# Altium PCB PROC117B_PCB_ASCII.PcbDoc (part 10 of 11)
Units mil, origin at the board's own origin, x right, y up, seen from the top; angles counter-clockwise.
Board outline 2480.32 x 3185.25 mil, 8 copper layers (Top Layer, L2_GND1, L3_SIG1, L4_PWR1, L5_PWR2, L6_SIG2, L7_GND2, Bottom Layer), stack 57.4 mil thick; 456 components, 292 nets, 7831 pads, 2905 vias.
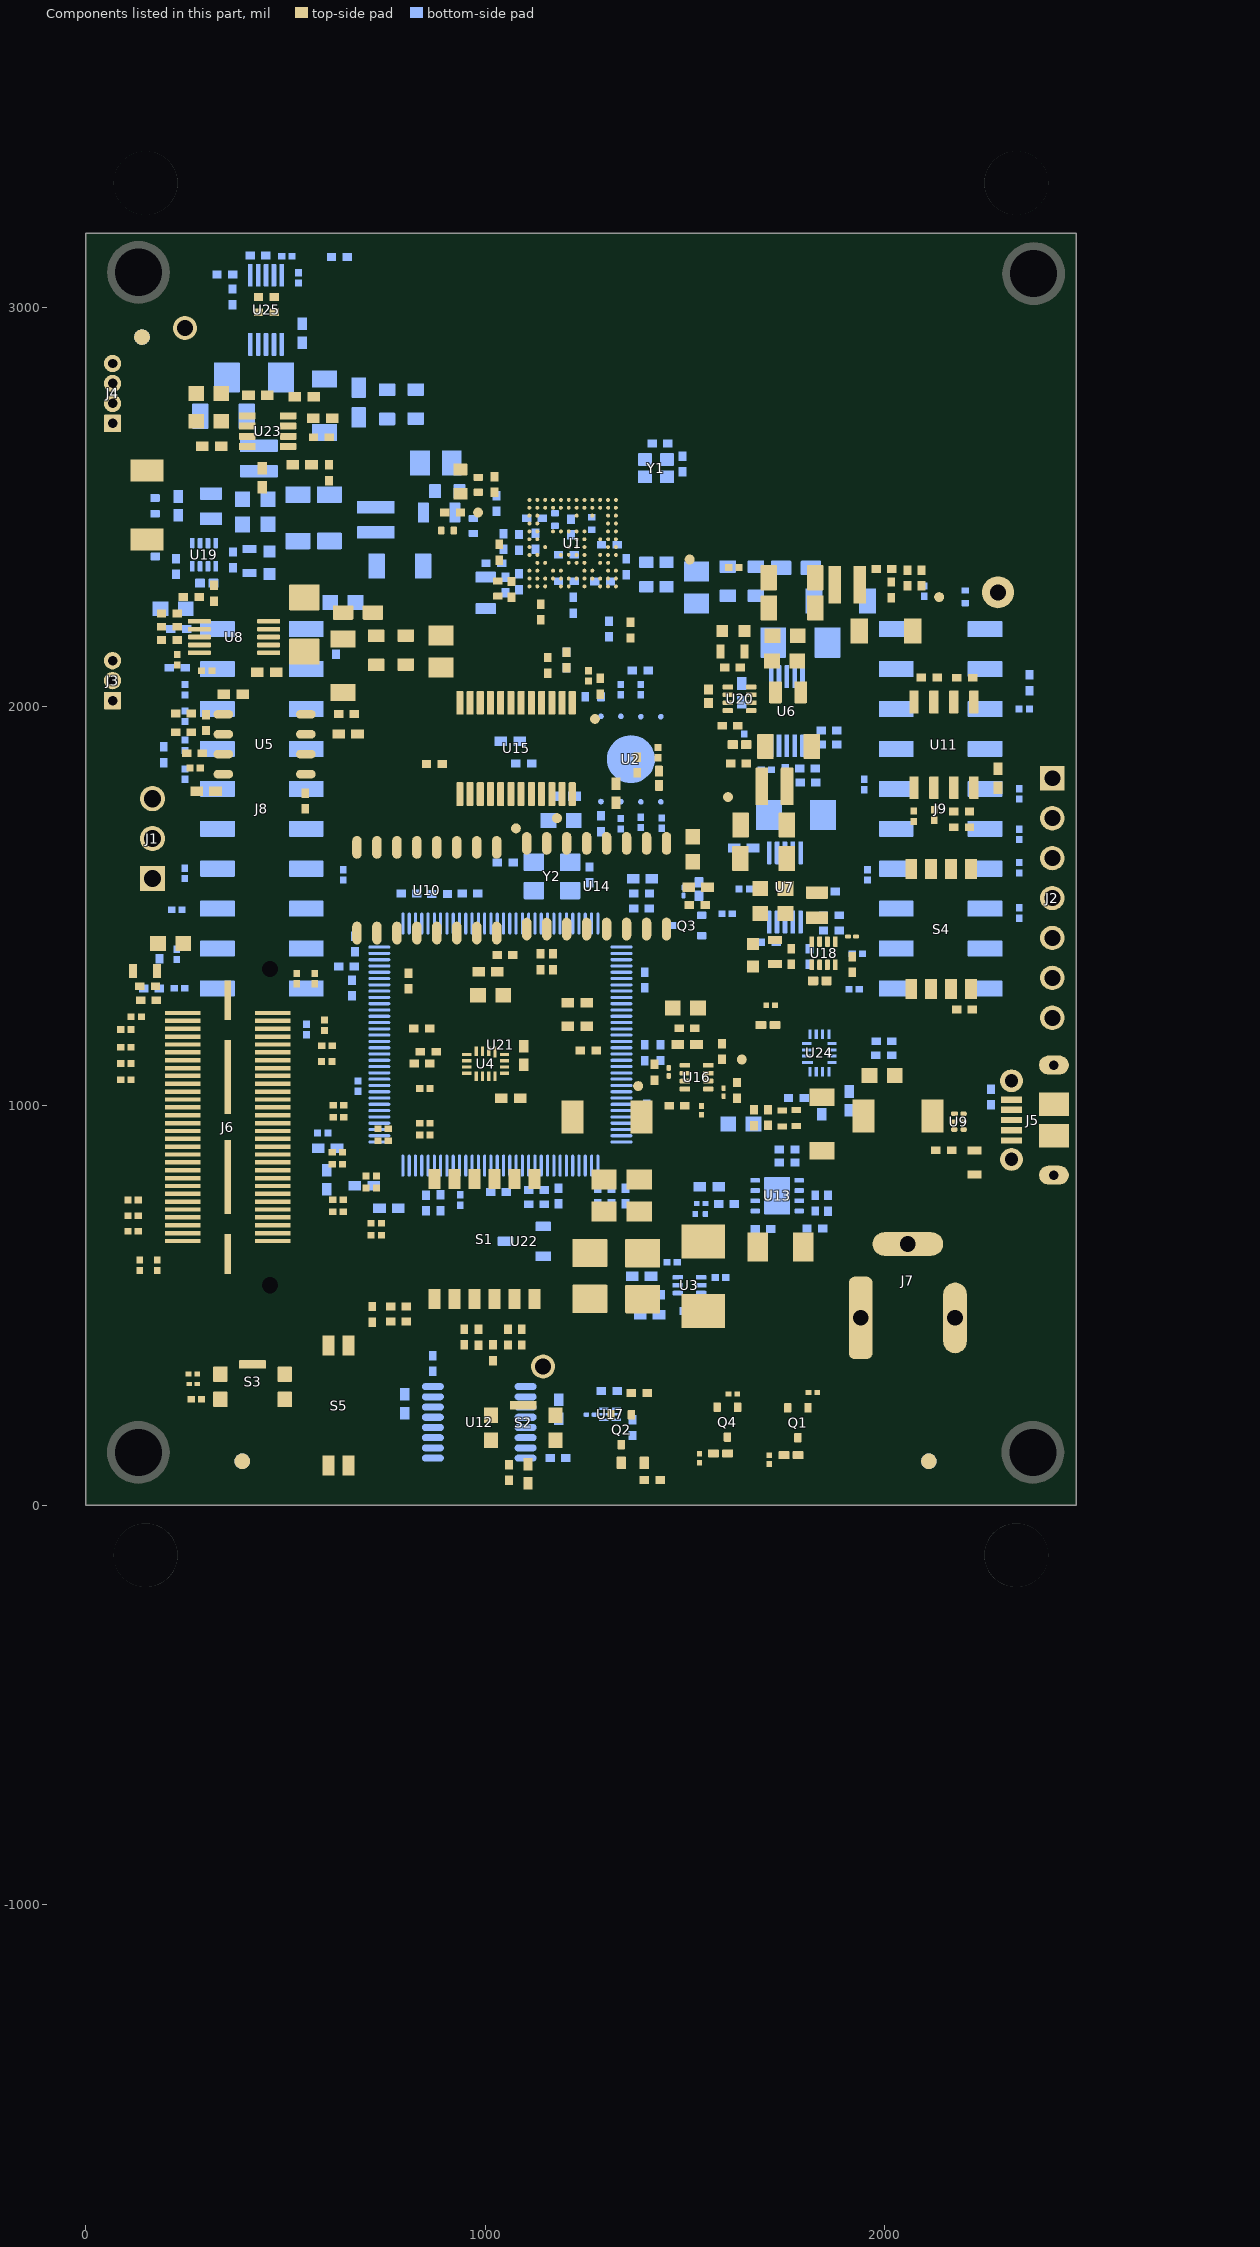
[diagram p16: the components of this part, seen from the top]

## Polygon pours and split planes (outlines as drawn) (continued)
GND on Bottom Layer "Bottom Layer-GND" (solid, remove dead copper, pour order 44876): 1820.82,706.99 1820.71,669.5 1699.27,669.5 1699.27,830.34 1692.44,837.17 1692.44,896.09 1702.05,905.7 1749.59,905.7 1751.32,903.97 1751.32,843.88 1764.94,830.26 1764.94,706.99
NetC117_1 on Bottom Layer "Bottom Layer-NetC117_1" (solid, remove dead copper, pour order 44880): 1816.62,797.83 1816.62,764.46 1887.3,764.46 1887.3,806.09 1824.88,806.09
GND on Top Layer "Top Layer-GND 4" (solid, remove dead copper, pour order 45126): 1043.73,2603.7 1043.73,2572.35 1097.54,2518.55 1097.54,2503.2 1110.73,2489.97 1132.89,2490.07 1136.38,2486.57 1150.08,2486.57 1152.21,2484.45 1287.29,2484.45 1287.29,2428.55 1296.77,2419.08 1296.66,2393.66 1299.9,2390.41 1311.73,2390.41 1320.87,2399.55 1320.87,2407.19 1379.01,2407.13 1395.17,2390.97 2494.07,2390.97 2494.07,3192.67 883.57,3192.67 883.57,2636.48 1010.94,2636.48
NetD2_2 on Top Layer "Top Layer-NetD2_2" (solid, remove dead copper, pour order 44824): 1188.41,843.93 1243.26,789.08 1419.49,789.08 1419.49,905.03 1313.99,905.03 1313.99,1025.58 1188.41,1025.58
5V_REG on Top Layer "Top Layer-5V_REG" (solid, remove dead copper, pour order 44812): 1472.31,1032.84 1472.87,1032.29 1472.87,924.8 1339.11,924.8 1339.11,1080.59 1475.81,1080.59 1489.41,1067.39 1522.55,1067.39 1542.24,1047.7 1571.4,1047.7 1571.4,1036.83 1535.28,1036.83 1515.55,1056.56 1489.79,1056.56 1472.31,1039.07
CONN_5V on Top Layer "Top Layer-CONN_5V" (solid, remove dead copper, pour order 45062): 161.03,1432.39 155.24,1438.18 141.96,1438.18 133.27,1446.87 133.27,1465.8 142.9,1475.42 161.03,1475.42 204.34,1475.36 204.34,1283.02 225.9,1261.46 288.1,1261.46 288.1,1206.63 199.33,1206.63 198.22,1205.52 194.33,1209.41 194.33,1221.65 161.03,1254.94
VBAT on Top Layer "Top Layer-VBAT" (solid, remove dead copper, pour order 45068): 43.62,2737.94 232.97,2737.94 238.92,2743.89 238.92,2756.13 248.19,2765.41 296.52,2765.41 296.52,2802.8 213.34,2802.8 213.34,2785.8 205.95,2778.4 51.48,2778.4 43.42,2770.33 43.42,2753.71
LIN_VDD on Top Layer "Top Layer-LIN_VDD" (solid, remove dead copper, pour order 45064): 312.88,2623.32 285.46,2623.32 113.7,2625.42 102.66,2614.38 102.66,2559.44 115.28,2546.82 380.44,2546.82 397.29,2563.67 397.29,2617.71 391.69,2623.32 366.57,2623.32 362.91,2626.97 362.91,2652.6 362.91,2799.88 360.12,2802.68 318.99,2802.46 316.42,2799.89 316.42,2692.08 322.51,2685.99 322.51,2632.94
SW1 on Top Layer "Top Layer-SW2" (solid, remove dead copper, pour order 44920): 1843.02,1398.04 1843.02,1450.93 1846.68,1454.59 1858.17,1454.59 1860.5,1456.91 1860.5,1485.71 1857.59,1488.62 1805.56,1488.62 1801.03,1484.09 1801.03,1458.19 1805.21,1454.01 1825.54,1454.01 1832.15,1447.39 1832.15,1398.04 1832.76,1398.19
GND on Top Layer "Top Layer-GND 6" (solid, remove dead copper, pour order 44842): 1630.23,2071.65 1629.91,1977.59 1620.24,1967.92 1620.24,1941.6 1651.08,1941.6 1651.09,1967.64 1644.45,1974.27 1644.45,2044.37 1690.31,2044.37 1700.77,2054.83 1700.77,2082.87 1708.66,2090.75 1740.39,2090.75 1740.39,2355.93 1626.91,2355.93 1626.91,2074.96
5V_IN on Top Layer "Top Layer-5V_IN" (solid, remove dead copper, pour order 44828): 1834.35,1331.43 1834.35,1297.72 1817.99,1281.36 1783.88,1281.33 1682.23,1281.33 1650.85,1249.95 1650.85,1136.35 1569.49,1136.77 1542.41,1109.7 1542.41,1091.15 1546.86,1086.71 1571.46,1086.71 1571.46,1075.61 1487.98,1075.61 1487.98,1087.09 1510.75,1087.09 1517.85,1094.18 1517.85,1110.27 1506.9,1121.22 1506.9,1358.76 1514.23,1366.08 1843.71,1366.08 1843.71,1340.79
SW3 on Top Layer "Top Layer-SW3" (solid, remove dead copper, pour order 44844): 1653.32,2023.09 1706.8,2023.09 1709.82,2020.07 1709.82,2008.57 1712.14,2006.25 1740.95,2006.25 1743.85,2009.15 1743.85,2061.18 1739.32,2065.71 1713.42,2065.71 1709.24,2061.53 1709.24,2041.21 1702.72,2034.69 1653.32,2034.69
5V_IN on Top Layer "Top Layer-5V_IN 2" (solid, remove dead copper, pour order 44846): 1520.58,2029.18 1586.76,2029.18 1592.3,2023.64 1620.87,2023.64 1620.87,2063.87 1613.04,2071.7 1613.04,2206.25 1520.58,2206.25
RADAR_1P2_RF on Top Layer "Top Layer-RADAR_1P2_RF" (solid, remove dead copper, pour order 45108): 1037.83,2499.59 1059.88,2499.59 1094.51,2464.95 1133.93,2464.95 1137.51,2461.38 1137.51,2451.67 1134.94,2449.1 1096.04,2449.1 1095.47,2448.54 1092.92,2446.2 1060.8,2446.2 1037.83,2469.17
NetC89_1 on Top Layer "Top Layer-NetC89_1" (solid, remove dead copper, pour order 45010): 1434.95,1467.98 1435.51,1467.42 1435.51,1422.03 1447.84,1409.71 1465.49,1409.71 1478.09,1422.31 1478.09,1462.93 1477.53,1463.49 1503.18,1489.14 1520.35,1489.14 1525.73,1494.52 1525.73,1580.54 1534.26,1589.07 1538.39,1589.07 1540.09,1590.77 1540.09,1630.1 1535.01,1635.18 1501.24,1635.18 1495.66,1629.6 1495.66,1564.03 1483.21,1551.58 1483.21,1518.13 1467.74,1502.66
CONN_5V on Top Layer "Top Layer-CONN_5V 1" (solid, remove dead copper, pour order 45116): 425.68,1280.4 423.17,1277.89 423.17,1228.23 424.36,1227.04 512.84,1227.04 512.84,1273.53 505.97,1280.4
RADAR_1V_RF_OUT on Top Layer "Top Layer-RADAR_1V_RF_OUT" (solid, remove dead copper, pour order 45006): 1057.66,2514.61 1057.71,2514.66 1066.37,2514.66 1082.94,2498.1 1087.11,2502.27 1087.11,2507.8 1046.75,2548.51 917.46,2548.51 917.46,2514.61
GND on Top Layer "Top Layer-GND 10" (solid, remove dead copper, pour order 45070): 87.57,1356.88 87.57,1249.12 147.72,1249.12 152.34,1253.75 152.34,1347.09 142.27,1357.16
GND on Top Layer "Top Layer-GND 12" (solid, remove dead copper, pour order 45110): 909.73,2612.17 909.73,2576.57 922.09,2564.22 1034.2,2564.22 1034.2,2600.73 1022.23,2612.69 1011.17,2612.69
REG_1V2 on Top Layer "Top Layer-REG_1V2 1" (solid, remove dead copper, pour order 45104): 518.63,2353.92 508.35,2343.64 508.35,2238.1 512.24,2234.21 581.63,2234.21 586.28,2238.86 586.28,2342.82 575.19,2353.92
RADAR_3V3 on Top Layer "Top Layer-RADAR_3V3" (solid, remove dead copper, pour order 45048): 1117.28,2316.83 1112.21,2311.76 1082.88,2311.76 1077.25,2306.14 1077.25,2301.3 1075.55,2299.6 1008.27,2299.6 997.05,2288.37 997.05,2281.76 990.85,2275.56 979.51,2275.56 974.1,2280.97 974.1,2299.3 997.84,2323.04 1052.31,2323.04 1054.81,2325.55 1114,2325.55 1117.28,2322.27
5V_IN on Top Layer "Bottom Layer-GND 6" (solid, remove dead copper, pour order 45076): 288.08,1388.29 288.08,1483.79 214.55,1483.79 214.55,1388.29
GND on Top Layer "Bottom Layer-GND 6" (solid, remove dead copper, pour order 45074): 676.86,2082.23 596.86,2082.23 596.86,2014.34 676.86,2014.34
GND on Top Layer "Top Layer-GND 11" (solid, remove dead copper, pour order 45046): 1107.69,2304.98 1089,2286.3 1021.8,2286.3 1015.19,2279.69 1007.27,2279.69 1001.65,2274.06 1001.65,2261.8 1006.5,2256.94 1054.54,2256.94 1063.1,2248.38 1063.1,2232.28 1058.7,2227.88 1058.7,2216.15 1064.08,2210.77 1074.26,2210.77 1078.59,2215.1 1078.59,2258.51 1116.93,2296.85 1116.93,2303.87 1114.45,2306.35 1108.96,2306.35 1108.44,2305.83
GND on Top Layer "Top Layer-GND 8" (solid, remove dead copper, pour order 45034): 2049.04,2156.72 2137.76,2156.72 2137.76,2221.52 2049.04,2221.52
GND on Top Layer "Top Layer-GND 9" (solid, remove dead copper, pour order 44924): 1591.33,1726.43 1601.57,1736.67 1657.66,1736.67 1667.78,1726.43 1719.41,1726.43 1719.41,1444.06 1822.36,1444.06 1822.36,1398.22 1831.93,1388.65 1937.14,1388.65 1937.14,1364.84 1932.27,1359.97 1908.73,1359.97 1893.34,1375.36 1631.52,1375.36 1631.52,1519.61 1591.33,1559.8
NetD1_2 on Top Layer "Top Layer-GND 2" (solid, remove dead copper, pour order 45032): 2147.68,1015.28 2019.75,1015.28 2019.75,864.08 2147.68,864.08
REG_OUT_3V3 on Top Layer "Top Layer-REG_OUT_3V3" (solid, remove dead copper, pour order 44922): 1859.78,1508.61 1859.78,1847.76 1732.2,1847.76 1732.2,1462.4 1772.61,1462.4 1772.61,1480.11 1801.12,1508.61
REG_3V3 on Top Layer "Top Layer-REG_3V3" (solid, remove dead copper, pour order 44834): 1639.75,1750.48 1720.3,1750.48 1720.3,1855.3 1729.22,1864.23 1729.22,1932.45 1639.75,1932.45
GND on Top Layer "Top Layer-GND 3" (solid, remove dead copper, pour order 44816): 1385.35,1116.16 1415.43,1086.08 1474.91,1086.08 1477.1,1088.45 1485.02,1096.37 1513.42,1096.37 1513.42,1106.88 1498.56,1121.74 1498.56,1267.91 1385.35,1267.91
NetC48_1 on Top Layer "Top Layer-NetC48_1" (solid, remove dead copper, pour order 44794): 1707.88,590.66 1215.94,590.66 1215.94,769.34 1430.36,769.34 1488.95,710.75 1707.93,710.75
5V_IN_USB on Top Layer "Top Layer-5V_IN_USB" (solid, remove dead copper, pour order 44802): 1589.76,1081.32 1601.36,1092.93 1988.55,1092.93 1989.6,1091.89 1989.6,930.61 1907.04,930.61 1906.66,976.33 1654.87,976.33 1654.93,1033.47 1649.1,1039.3 1586.39,1039.3 1580.9,1044.79 1568.82,1056.87 1545.61,1056.87 1545.61,1067.93 1572.06,1067.93
GND on Top Layer "Top Layer-GND 1" (solid, remove dead copper, pour order 44820): 1218.4,554.98 1218.4,369.71 1600.95,369.71 1600.95,554.98
GND on Top Layer "Top Layer-GND 8" (solid, remove dead copper, pour order 44926): 1796.54,1867.62 1885.25,1867.62 1885.25,1932.42 1796.54,1932.42
VCC_3V3 on Top Layer "Top Layer-GND 8" (solid, remove dead copper, pour order 44944): 1630.26,1883.71 1546.99,1883.71 1546.99,1803.29 1630.26,1803.29
REG_1V8 on Top Layer "Top Layer-REG_1V8" (solid, remove dead copper, pour order 45026): 1995.09,2355.56 1911.68,2355.56 1911.68,2231.43 1878.36,2198.11 1878.36,2119.16 1995.09,2119.16
REG_OUT_1V8 on Top Layer "Top Layer-REG_OUT_3V3" (solid, remove dead copper, pour order 44836): 1858.01,2207.19 1894.52,2243.7 1894.52,2359.42 1753.96,2359.42 1753.91,2005.65 1858.01,2006.09
CB_REG_1V2 on Top Layer "Top Layer-CB_REG_1V2" (solid, remove dead copper, pour order 45022): 508.13,2180.89 508.13,2105.19 679.39,2105.19 679.39,2266.51 603.6,2266.51 603.6,2188.22 596.85,2181.47
RADAR_1V2 on Top Layer "Bottom Layer-RADAR_1V2" (solid, remove dead copper, pour order 44960): 932.72,2152.04 932.47,2276.03 695.42,2276.03 695.42,2152.04 775,2152.04
GND on Top Layer "Bottom Layer-GND 1" (solid, remove dead copper, pour order 44966): 923.96,2050.81 923.96,2124.44 706.03,2124.44 706.03,2050.81
USB_5V on Top Layer "Top Layer-No Net 1" (solid, remove dead copper, pour order 45016): 2275.19,876.81 2275.19,850.64 2248.08,850.64 2154.74,850.64 2154.74,906.51 2259.76,906.51 2275.32,922.07 2344.62,922.07 2344.65,904.73 2343.85,903.93 2302.31,903.93
NetC75_1 on Top Layer "Top Layer-NetC75_1" (solid, remove dead copper, pour order 45012): 1014.18,1319.62 1014.18,1250.64 1028.82,1236 1068.28,1236 1077.3,1245.01 1077.3,1321.76 1044.67,1354.39 1044.67,1460.22 1037.46,1467.43 1014.18,1467.43
GND on Top Layer "Top Layer-GND 2" (solid, remove dead copper, pour order 44818): 1897.2,851.36 1897.2,963.6 1660.69,963.6 1660.69,851.36
GND on Top Layer "Top Layer-GND" (solid, remove dead copper, pour order 44822): 2286.75,755.41 2278.43,763.73 2179.46,763.73 2159.63,783.56 2159.63,826.43 2172.3,839.1 2281.76,839.1 2286.75,843.97 2286.75,876.44 2304.85,894.54 2356.45,894.54 2372.72,910.8 2372.72,991.52 2357.97,1006.27 2290.21,1006.27 2275.55,1020.93 2276.04,1142.41 2455.84,1142.41 2472.93,1125.32 2472.93,591.16 2450.33,568.56 2360.72,568.56 2329.75,599.54 2329.75,712.41
GND on Top Layer "Top Layer-GND 5" (solid, remove dead copper, pour order 44806): 1968.46,692.06 1968.46,623.75 2005.54,586.67 2005.54,379.61 2305.41,379.61 2305.41,692.06
NetF1_2 on Top Layer "Top Layer-NetF1_2" (solid, remove dead copper, pour order 44792): 1750.6,692.16 1945.45,692.16 1945.45,613.84 1977.95,581.34 1977.95,363.39 1750.6,363.39
GND on L5_PWR2 "L5_SIGNAL 3-GND" (solid, remove dead copper, pour order 45134): 0,3185.25 2480.32,3185.25 2480.32,0 0,0
5V_IN on L5_PWR2 "L5_SIGNAL 3-5V_IN" (solid, remove dead copper, pour order 45088): 312.76,1695.03 218.28,1600.54 218.28,1447.04 231.19,1434.12 314.65,1434.12 422.7,1542.18 422.7,1637.76 460.78,1675.9 1229.57,1675.9 1544.07,1361.39 1544.07,797.92 1898.55,797.92 1898.55,2196.54 756.65,2215.53 752.14,2211.02 670.17,2293 659.51,2293 594.24,2358.27 312.76,2358.27
VCC_XDS_3V3 on L5_PWR2 "L5_SIGNAL 3-VCC_XDS_3V3" (solid, remove dead copper, pour order 45092): 1510.15,1446.97 1271.82,1654.16 743.81,1654.16 743.81,939.52 790.3,893.03 790.3,589.85 968.8,411.35 1765.64,411.35 1876.97,522.67 1876.97,639.01 1878.81,639.01 1949.44,709.63 1949.44,748.98 1930.35,768.06 1928.45,766.15 1856.87,766.15 1796.75,706.03 1553.96,706.03 1510.15,749.84 1510.15,803.46
RADAR_1V8 on L5_PWR2 "L6_SIGNAL 4-RADAR_1V8" (solid, remove dead copper, pour order 45094): 831.76,2241.04 1636.41,2241.04 1636.41,2373.32 1335.13,2373.32 1272.33,2436.12 1248.99,2436.12 1242.66,2442.45 1242.99,2463.45 1232.53,2473.91 1149.43,2473.91 1135.58,2460.06 831.76,2460.06 831.76,2395.84
CONN_5V on L5_PWR2 "L5_SIGNAL 3-CONN_5V" (solid, remove dead copper, pour order 45132): 125.28,1458.31 125.28,1452.78 156.83,1421.23 156.83,1280.07 211.02,1225.88 479.13,1225.88 494.34,1241.09 494.34,1265.18 416.09,1343.43 289.79,1343.43 199.95,1433.27 199.95,1455.42 165.57,1489.81 153.05,1489.81
GND on L2_GND1 "L2_GND-GND" (solid, remove dead copper, pour order 44786): 2480.32,2338.95 2480.32,0 0,0 0,3185.25 2480.32,3185.25
GND on L7_GND2 "L7_GND-GND" (solid, remove dead copper, pour order 44788): 0,3185.25 2480.32,3185.25 2480.32,0 0,0
GND on L3_SIG1 "L3_SIGNAL 1-GND" (solid, remove dead copper, pour order 45128): 0,3185.25 2480.32,3185.25 2480.32,0 0,0

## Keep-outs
Keep-Out Layer:
  circle w1: c460.74,1343.14 r32
  circle w1: c460.74,550.62 r32
  text ".Layer_Name" at -304.89,-799.23 h60

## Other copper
Top Layer:
  text ".Layer_Name" at -304.89,-799.23 h60
L2_GND1:
  text ".Layer_Name" at -304.89,-799.23 h60
L3_SIG1:
  text ".Layer_Name" at -304.89,-799.23 h60
L5_PWR2:
  text ".Layer_Name" at -304.89,-799.23 h60
L7_GND2:
  text ".Layer_Name" at -304.89,-799.23 h60
L4_PWR1:
  text ".Layer_Name" at -304.89,-799.23 h60
L6_SIG2:
  text ".Layer_Name" at -304.89,-799.23 h60
Bottom Layer:
  text ".Layer_Name" at -304.89,-799.23 h60

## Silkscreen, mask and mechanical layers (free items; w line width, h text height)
Top Overlay:
  circle w1.51: c773.45,2452.58 r4.71
  circle w1.51: c773.45,2452.58 r4.71
  circle w15: c307.59,2004.64 r3.1
  circle w15: c2276.6,896.74 r3.1
  circle w15: c199.16,1251.24 r3.1
  circle w20: c257.99,2251.06 r3.1
  circle w15: c1597.99,2075.3 r3.1
  circle w15: c2271.78,2026.9 r3.1
  circle w15: c2250.19,1594.13 r3.1
  circle w15: c1885.88,394.93 r3.1
  circle w15: c831.03,517.88 r3.1
  circle w15: c1433.47,1684.68 r3.36
  circle w10: c1024.93,1163.14 r1.86
  circle w15: c1028.72,1693.59 r3.1
  lines w0.38: 766.41,2446.6 721.91,2431.54 766.41,2446.6 ; 766.41,2446.6 724.71,2425.94 766.41,2446.6
  lines w0.76: 763.61,2445.39 758.54,2443.65 763.61,2445.39 ; 763.61,2445.39 758.23,2442.97 763.61,2445.39
  lines w1.51: 758.23,2443.2 722.89,2431.16 758.23,2443.2 ; 758.23,2443.2 724.33,2426.7 758.23,2443.2
  lines w3.03: 728.42,2429.95 725.39,2431.01 728.42,2429.95 ; 728.42,2429.95 721.53,2427.46 728.42,2429.95 ; 651.23,2459.47 655.39,2461.59 651.23,2459.47 ; 724.18,2429.27 746.28,2438.2 724.18,2429.27
  lines w4: 872.01,2319.56 872.01,2419.56 ; 872.01,2444.56 872.01,2544.56 ; 872.01,2569.56 872.01,2669.56 ; 872.01,2694.56 872.01,2794.56 ; 872.01,2819.56 872.01,2919.56 ; 872.01,2944.56 872.01,3044.56 ; 872.01,3069.56 872.01,3169.56 ; 875.87,2294.12 967.32,2202.67 ; 987.65,2195.46 1087.65,2195.46 ; 1112.65,2195.46 1212.65,2195.46 ; 1237.65,2195.46 1337.65,2195.46 ; 1370.2,2378.1 1470.2,2378.1 ; 1495.2,2378.1 1595.2,2378.1 ; 1620.2,2378.1 1720.2,2378.1 ; 1746.49,2378.5 1846.49,2378.5
  lines w6: 132.24,2266.67 140.52,2274.95 140.52,2258.32 132.17,2266.67 149.98,2266.67 168.15,2248.5 168.15,2167.46
  lines w6.81: 622.62,2433.89 626.78,2438.13 ; 622.62,2433.89 626.78,2438.13 ; 622.62,2433.89 616.26,2426.85 622.62,2433.89 ; 626.78,2438.13 630.57,2441.76 ; 626.78,2438.13 630.57,2441.76 ; 630.57,2441.76 632.53,2443.65 ; 630.57,2441.76 632.53,2443.65 ; 632.53,2443.65 637.08,2447.28 ; 632.53,2443.65 637.08,2447.28 ; 637.08,2447.28 641.31,2450.76 ; 637.08,2447.28 641.31,2450.76 ; 641.31,2450.76 642.98,2451.9 ; 641.31,2450.76 642.98,2451.9 ; 642.98,2451.9 644.95,2453.11 ; 642.98,2451.9 644.95,2453.11 ; 644.95,2453.11 648.05,2455.08 644.95,2453.11 ; 651.98,2457.8 644.64,2453.11 651.98,2457.8 ; 651.98,2457.8 644.34,2453.03 651.98,2457.8 ; 657.43,2434.57 ccw(c661.61,2431.38) 664.92,2427.3 ; 657.43,2434.57 ccw(c661.61,2431.38) 664.92,2427.3 ; 657.43,2434.57 672.19,2453.94 ; 657.43,2434.57 672.19,2453.94 ; 660.69,2462.04 664.55,2463.63 ; 660.69,2462.04 664.55,2463.63 ; 660.69,2462.04 655.69,2459.62 660.69,2462.04 ; 664.55,2463.63 cw(c667.96,2456.35) 671.96,2463.33 ; 664.55,2463.63 cw(c667.96,2456.35) 671.96,2463.33 ; 664.92,2427.3 cw(c773.83,2237.51) 709.8,2446.75 ; 664.92,2427.3 cw(c773.83,2237.51) 709.8,2446.75 ; 671.96,2463.33 cw(c670.3,2460.42) 673.55,2461.21 ; 671.96,2463.33 cw(c670.3,2460.42) 673.55,2461.21 ; 672.19,2453.94 ccw(c664.79,2459.09) 673.55,2461.21 ; 672.19,2453.94 ccw(c664.79,2459.09) 673.55,2461.21 ; 709.8,2446.75 cw(c710.55,2441.28) 715.93,2442.52 ; 709.8,2446.75 cw(c710.55,2441.28) 715.93,2442.52 ; 715.93,2442.52 cw(c694.6,2437.64) 716.16,2433.89 ; 715.93,2442.52 cw(c694.6,2437.64) 716.16,2433.89 ; 716.16,2433.89 ccw(c721.08,2433.03) 722.67,2428.29 cw(c721.08,2433.03) 716.16,2433.89 ; 646.84,2454.24 649.64,2456.14 646.84,2454.24 ; 648.28,2455.46 653.65,2458.41 648.28,2455.46
  text "GND" at 188.05,2982.15 h25
  text "PROC117 REV. B" at 339.8,2902.51 h60
  text "ENGINE AREA" at 852.19,2679.29 h25 r90
  text "LIN_HEADER" at 125.69,2638.42 h25 r90
  text "R" at 771.71,2450.61 h4.54
  text "R" at 771.71,2450.61 h4.54
  text "GPADC1" at 944.36,2439.33 h25
  text "MISTRAL" at 617.06,2385.37 h41.62
  text "OSC_CLKOUT" at 1358.97,2303.4 h25
  text "GPADC2" at 2097.87,2223.27 h25
  text "VPP_1P7" at 2265.55,2196.24 h25
  text "ENGINE AREA" at 942.45,2156.66 h25
  text "CAN_HEADER" at 124.83,1937.94 h25 r90
  text "WD_TP" at 1260.77,1916.15 h25
  text "VCC_3V3" at 1507.12,1791.38 h25
  text "nERR_LED" at 1491.62,1777.52 h25 r90
  text "RTC_CLKIN" at 841.39,1716.5 h25
  text "HOST_CLK" at 1266.4,1699.38 h25
  text "I2C_HEADER" at 89.55,1536.91 h25 r90
  text "TEXAS" at 345.46,1490.22 h25
  text "INSTRUMENTS" at 300.02,1447.39 h25
  text "SPI_HEADER" at 2356.45,1276.73 h25 r90
  text "5V_LED" at 1753.45,1198.2 h25
  text "LIN_EN" at 2127.18,1121.91 h25 r90
  text "SW_ST" at 1659.75,1108.44 h25
  text "CAN_EN" at 2182.9,1087.86 h25 r90
  text "MODE_SEL" at 1334.59,1075.38 h25 r90
  text "XDS/DCA" at 2272.33,1043.03 h25 r90
  text "LVDS" at 984.6,847.22 h25 r90
  text "RS232" at 1036.05,846.73 h25 r90
  text "CAN/" at 1118.48,842.73 h25 r90
  text "I2C/SPI" at 1165.17,822.09 h25 r90
  text "USB_5V" at 2290.52,745.25 h25
  text "DCA1000_CONN" at 259.09,485.61 h25
  text "5V_PWR" at 1747.01,473.34 h25
  text "S0P1" at 926.04,396.3 h25 r90
  text "S0P0" at 884.5,392.78 h25 r90
  text "USER_SW" at 338.81,387.41 h25
  text "PMIC_CLKOUT" at 1074.57,285.43 h25
  text "RESET_LED" at 1825.66,117.58 h25
  text "XDS_I2C_SW" at 744.2,104.58 h25 r90
  text "RESET_SW" at 928.32,104.58 h25 r90
  text "USER_LED" at 1523.64,58.36 h25
  text "PGOOD" at 1247.37,42.69 h25
  text ".Layer_Name" at -304.89,-799.23 h60
Bottom Overlay:
  circle w15: c1350.5,262.57 r3.1
  circle w15: c1790.12,1425.22 r3.1
  circle w15: c389.39,3112.89 r3.1
  circle w15: c306.05,2229.73 r3.1
  circle w15: c1809.94,1867.07 r3.1
  circle w15: c1563.25,592.16 r3.1
  circle w15: c1960.23,2197.79 r3.1
  circle w15: c1776.64,1094.99 r3.1
  circle w15: c1815.61,817.08 r3.1
  circle w15: c814.56,117.78 r3.1
  region: 311.84,1171.06 311.84,482.62 410.08,482.62 410.08,1171.06
  lines w4: 719.27,2690.03 789.98,2619.32 ; 773.42,2847.34 844.13,2918.05 ; 818.52,2406.64 918.52,2406.64 ; 862.79,2935.17 862.79,3035.17 ; 862.79,3060.17 862.79,3160.17 ; 923.25,2296.56 923.25,2396.56 ; 923.78,2181.19 923.78,2281.19 ; 926.9,2153.7 1026.9,2153.7 ; 1045.01,2153.16 1145.01,2153.16 ; 1164.19,2154.24 1230.02,2154.35 ; 1254.94,2191.25 1303.94,2238.99 ; 1332.31,2235.26 1432.31,2235.26 ; 1437.66,2212.35 1537.66,2212.35 ; 1553.39,2211.83 1653.39,2211.83 ; 1702.05,2223.97 1772.76,2294.68 ; 1868.11,2315.74 1938.82,2386.45 ; 1953.74,2387.27 2053.74,2387.27 ; 2071.11,2387.27 2171.11,2387.27 ; 2189.39,2387.91 2289.39,2387.91 ; 2315.98,2387.16 2415.98,2387.16
  lines w6: 329.11,2573.37 333.59,2577.86 ; 338.08,2573.37 333.59,2577.86 ; 487.05,2556.04 482.56,2560.53 333.59,2560.53 333.59,2577.86 ; 1180.84,1930.95 1180.84,1951.04
  lines w10: 311.84,483.17 410.08,483.17 ; 411.99,344.87 411.99,1171.06 311.99,1171.06 311.99,344.87 412.13,344.87
  text "GND" at 278.02,2988.36 h25
  text "LIN" at 22.9,2913 h60 r270
  text "ENGINE AREA" at 778.57,2891.55 h25 r270
  text "GND" at 170.33,2845.91 h25
  text "LIN_BUS" at 260.97,2795.74 h25
  text "VBAT" at 191.91,2747.18 h25
  text "5V_IN" at 218.89,2695.39 h25
  text "3V3" at 132.35,2166.2 h60
  text "ENGINE AREA" at 1213.16,2166.74 h25
  text "GND" at 2431.2,2166.6 h60
  text "5V" at 768.66,2154.22 h60
  text "CANH" at 190.16,2115.34 h25
  text "GND" at 164.5,2050.65 h25
  text "CANL" at 141.38,1954.31 h25
  text "GND" at 271.68,1767.21 h25
  text "SDA" at 272.54,1654.77 h25
  text "SCL" at 187.58,1507.07 h25
  text "FY21-22/02737000102" at 1058.76,500 h28
  text "SL#" at 340.35,360.28 h70 r270
  text ".Layer_Name" at -304.89,-799.23 h60
Top Paste:
  text ".Layer_Name" at -304.89,-799.23 h60
Bottom Paste:
  text ".Layer_Name" at -304.89,-799.23 h60
Top Solder:
  text ".Layer_Name" at -304.89,-799.23 h60
  text ".Layer_Name" at -304.89,-799.23 h60
Bottom Solder:
  text ".Layer_Name" at -304.89,-799.23 h60
Drill Guide:
  text ".Layer_Name" at -304.89,-799.23 h60
M1 Board Outline:
  lines w2: 0,-0.01 0,-275.6 2480.32,-275.6 2480.32,0 ; 0,0 0,3185.25 ; 0,0 2480.32,0 ; 0,3185.25 0,3460.85 2480.32,3460.85 2480.32,3185.26 ; 0,3185.25 2480.32,3185.25 ; 2480.32,0 2480.32,3185.25
  text ".Layer_Name" at -311.49,-722.54 h40
M2 Board Dimensions:
  text ".Layer_Name" at -316.77,-797.29 h60
M3 3D STEP Top:
  text ".Layer_Name" at -304.89,-799.23 h60
M4 3D STEP Bottom:
  text ".Layer_Name" at -304.89,-799.23 h60
M5 Assembly Top:
  circle w4: c1608.13,1773.05 r15
  circle w4: c248.36,2947.57 r35.35
  lines w10: -1173.89,-870.9 5426.11,-870.9 ; -1173.89,-667.57 5428.11,-667.57 ; -1173.89,-464.24 -1173.89,-1074.24 2831.11,-1074.24 5428.11,-1074.24 5428.11,-464.24 -1173.39,-464.24 -1173.39,-1074.24 402.11,-1074.24 ; 1291.11,-1074.24 1291.11,-464.24 ; 2558.11,-667.57 2558.11,-464.24 ; 3398.11,-667.57 3398.11,-464.24 ; 4020.11,-1080.74 4020.11,-877.9
  text "COMPONENTS MARKED 'DNP' SHOULD NOT BE POPULATED." at -50.63,3649.59 h60
  text "ASSEMBLY VARIANT:" at -51.13,3534.09 h60
  text ".VariantName" at 984.87,3534.09 h60
  text "GND" at 204.98,2996.63 h25
  text "TP11" at 205.31,2879.08 h25
  text "VCC_3V3" at 1483.97,1799.93 h25
  text "TP9" at 1508.89,1757.45 h25
  text "PCB VIEWED FROM TOP SIDE" at -1110.39,-596.4 h60
  text "BOARD #:" at 1366.11,-596.4 h60
  text ".PRJ_Number" at 1911.61,-596.4 h60
  text "REV:" at 2756.11,-596.4 h60
  text ".PCB_Rev" at 3047.61,-596.4 h60
  text "SVN REV:" at 3594.11,-596.4 h60
  text ".VersionControl_RevNumber" at 4100.11,-596.4 h60
  text "Assembly Layer Top" at -314.89,-795.74 h60
  text "TID #:" at 1366.11,-799.74 h60
  text ".TID" at 1911.61,-799.74 h60
  text "PLOT NAME =" at -1110.39,-1005.07 h60
  text ".plot_File_Name" at -304.89,-1005.07 h60
  text "GENERATED    :" at 1368.11,-1005.07 h60
  text ".Print_Date" at 2237.61,-1005.07 h60
  text ".Print_Time" at 2966.61,-1005.07 h60
  text "TEXAS INSTRUMENTS" at 4231.11,-1005.07 h60
M6 Assembly Bottom:
  circle w4: c1607.98,1773.11 r15
  circle w4: c248.36,2947.57 r32.81
  lines w10: -1174.39,-668.07 5427.61,-668.07 ; -1172.39,-871.4 5427.61,-871.4 ; 233.61,-1081.24 233.61,-878.4 ; 855.61,-668.07 855.61,-464.74 ; 1695.61,-668.07 1695.61,-464.74 ; 2962.61,-1074.74 2962.61,-464.74 ; 3851.61,-1074.74 5427.11,-1074.74 5427.11,-464.74 -1174.39,-464.74 -1174.39,-1074.74 1422.61,-1074.74 5427.61,-1074.74 5427.61,-464.74
  text "GND" at 279.85,2987.43 h25
  text "TP11" at 293.64,2880.06 h25
  text "VCC_3V3" at 1650.41,1795.47 h25
  text "TP9" at 1578.18,1758.91 h25
  text "COMPONENTS MARKED 'DNP' SHOULD NOT BE POPULATED." at 5424.69,-241.69 h60
  text ".VariantName" at 4380.69,-357.69 h60
  text "ASSEMBLY VARIANT:" at 5419.69,-357.69 h60
  text ".VersionControl_RevNumber" at 153.61,-596.9 h60
  text "SVN REV:" at 659.61,-596.9 h60
  text ".PCB_Rev" at 1206.11,-596.9 h60
  text "REV:" at 1497.61,-596.9 h60
  text ".PRJ_Number" at 2342.11,-596.9 h60
  text "BOARD #:" at 2887.61,-596.9 h60
  text "PCB VIEWED FROM BOTTOM SIDE" at 5364.11,-596.9 h60
  text "Assembly Bottom Layer" at 5003.11,-785.74 h60
  text ".TID" at 2342.11,-800.24 h60
  text "TID #:" at 2887.61,-800.24 h60
  text "TEXAS INSTRUMENTS" at 22.61,-1005.57 h60
  text ".Print_Time" at 1287.11,-1005.57 h60
  text ".Print_Date" at 2016.11,-1005.57 h60
  text "GENERATED    :" at 2885.61,-1005.57 h60
  text ".plot_File_Name" at 4558.61,-1005.57 h60
  text "PLOT NAME =" at 5364.11,-1005.57 h60
M7 LPKF Text Top:
  lines w2: 1125.99,2272.42 1157.47,2272.42 ; 1133.86,2272.42 1149.6,2272.42 ; 1141.73,2256.68 1141.73,2288.16 ; 1141.73,2264.55 1141.73,2280.29
M9 Title Sheet:
  lines w10: 1126.61,8025.76 1126.61,8225.76 ; 3626.61,8025.76 3626.61,8225.76
  text "1" at -142.05,8095.76 h70
  text "2" at 2353.61,8095.76 h70
M10 Fab Notes:
  drawing of 348 lines, arcs and shapes, not listed
  text "3" at 4842.96,8095.76 h70
  text "4" at 7349.62,8095.76 h70
  text "5" at 9848.61,8095.76 h70
  text "6" at 12353.61,8095.76 h70
  text "A" at -1298.39,6952.76 h70
  text "A" at 13501.61,6952.76 h70
  text "DESIGN INFORMATION" at 11500.13,6415.44 h60
  text "3.9" at 11894.61,6286.04 h60
  text "MIN. TRACK WIDTH:" at 10855.57,6283.31 h60
  text "MIL" at 12106.57,6283.31 h60
  text "3.9" at 11892.07,6166.66 h60
  text "MIN. CLEARANCE:" at 10855.57,6159.19 h60
  text "MIL" at 12106.57,6159.19 h60
  text "MIN. VIA PAD SIZE:" at 10855.57,6035.06 h60
  text "18" at 11878.26,6027.69 h60
  text "MIL" at 12129.11,6026.26 h60
  text "EXTERNAL" at 12376.71,5907.75 h60
  text "0.127mm (5.0MIL)" at 11550.57,5905.16 h60
  text "MINIMUM ANNULAR RING" at 10526.34,5896.94 h60
  text "PER" at 10726.34,5786.81 h60
  text "IPC-D-275 CLASS 2 LEVEL C" at 10946.34,5786.81 h60
  text "MIL, HOLES" at 12434.57,5686.33 h60
  text "+/-" at 12042.11,5677.75 h60
  text "+/-" at 12896.11,5677.75 h60
  text "REGISTRATION TOLERANCES:" at 10526.34,5676.68 h60
  text "METAL" at 11726.11,5676.68 h60
  text "5" at 12302.31,5676.68 h60
  text "3" at 13135.31,5676.68 h60
  text "MIL" at 13251.57,5676.68 h60
  text "45" at 5229,5630.06 h80
  text "HOLE SIZE TOLERANCE (UNLESS OTHERWISE SPECIFIED):" at 10526.34,5578.37 h60
  text "+/-" at 12896.11,5575.49 h60
  text "3" at 13135.31,5574.43 h60
  text "MIL" at 13251.57,5574.43 h60
  text "TYP" at 5189,5465.06 h80
  text "MATERIAL:" at 10451.57,5436.78 h60
  text "FR-4 High Tg" at 11438.02,5308.26 h60
  text "X" at 12180.11,5303.26 h60
  text "REFER STACK-UP" at 12680.96,5302.67 h55
  text "FR-408" at 10872.57,5295.75 h60
  text "OTHER" at 12360.57,5295.75 h60
  text "0.55MM" at 4148.59,5251.73 h80
  text "X" at 12351.12,5155.27 h60
  text "62 MIL (1.6mm) +/-10%" at 11192.67,5152.72 h60
  text "59 MIL +/-10%" at 12773.11,5146.26 h45
  text "THICKNESS:" at 10526.34,5144.5 h60
  text "OTHER" at 12477.57,5144.5 h60
  text "TOLERANCE:" at 10526.34,5006.19 h60
  text "X" at 11374.58,5006.19 h60
  text "ANSI IPC-6012 TYPE 3 CLASS 2" at 11552.59,5006.19 h60
  text "OTHER +/-" at 11552.57,4862 h60
  text "1.50MM" at 3518.59,4786.73 h80
  text "0.50MM" at 6366.5,4786.73 h80
  text "BOW & TWIST:" at 10526.34,4716.81 h60
  text "X" at 11374.58,4716.81 h60
  text "ANSI IPC-6012 TYPE 3 CLASS 2" at 11552.59,4716.81 h60
  text "B" at -1298.39,4572.76 h70
  text "B" at 13501.61,4572.76 h70
  text "OTHER +/-" at 11552.57,4570.11 h60
  text "DRILLING:" at 10451.57,4439.49 h60
  text "NC_DRILL FILES" at 12212.57,4334.3 h60
  text "REFERENCE:" at 10526.34,4330.37 h60
  text "X" at 11183.58,4330.27 h60
  text "AS SHOWN" at 11361.57,4330.37 h60
  text "X" at 12084.58,4330.37 h60
  text "0.10MM" at 4738.59,4207.56 h80
  text "OTHER" at 12510.57,4188.11 h60
  text "PTH COPPER THICKNESS:" at 10526.02,4184.59 h60
  text "X" at 11665.25,4184.59 h60
  text "20-30 um" at 11793.25,4184.59 h60
  text "DETAIL-A(V-GROOVE DETAILS)" at 4221.09,4045.43 h80
  text "BOARD FINISH:" at 10451.57,4036.99 h60
  text "SILKSCREEN:" at 10606.79,3926.86 h60
  text "X" at 11564.58,3926.86 h60
  text "TOP" at 11681.57,3926.86 h60
  text "X" at 12074.58,3926.86 h60
  text "BOTTOM" at 12192.57,3926.86 h60
  text "SCALE : NTS" at 4733.27,3904.87 h80
  text "NOTES:" at 3540.45,3818.29 h60
  text "SILKSCREEN COLOR:" at 10606.79,3771.67 h60
  text "X" at 11563.58,3771.67 h60
  text "WHITE" at 11681.57,3771.67 h60
  text "OTHER" at 12192.57,3771.67 h60
  text "1. BOARD SHALL MEET THE REQUIREMENTS OF UL-796E WITH FLAMMABILITY RATING OF MINIMUM 94V-0. UL LOGO," at 3567.2,3672.46 h60
  text "GREEN" at 11812.57,3628.23 h60
  text "X" at 12286.58,3628.23 h60
  text "OTHER" at 12430.57,3628.23 h60
  text "RED" at 12803.11,3628.23 h60
  text "SOLDER RESIST COLOR:" at 10606.79,3621.36 h60
  text "MANUFACTURER'S IDENTIFICATION AND DATE CODE LETTER SHALL BE RENDERED IN SILKSCREEN." at 3673.93,3573.46 h60
  text "MATTE" at 11812.57,3473.97 h60
  text "SEMI-GLOSS" at 12430.11,3473.34 h60
  text "X" at 12286.18,3471.28 h60
  text "2. VENDOR MAY ADJUST SOLDERMASK WHEREVER SOLDERMASK PADS ARE THE SAME SIZE (1:1) AS PER THE MANUFACTURING CAPABILITIES" at 3560.21,3447.68 h60
  text "AND ALL OTHER SOLDER MASK PADS SHALL NOT BE MODIFIED, PROVIDED NO ADJACENT COPPER IS EXPOSED AND NO CONFLICT IS PRODUCED" at 3666.94,3348.68 h60
  text "IMMERSION GOLD (ENIG)" at 11512.57,3301.2 h60
  text "ENEPIG" at 12850.11,3293.98 h60
  text "SURFACE FINISH:" at 10451.57,3292.98 h60
  text "REFER DETAIL-A" at 2740.17,3279.52 h40
  text "WITH ANY STATED \"VIA TENTING/COVERING\" REQUIREMENTS." at 3666.94,3255.4 h60
  text "IMM. SILVER" at 12627.5,3165.34 h60
  text "IMM. TIN/SILVER OR EQUIV" at 10781.11,3155.67 h60
  text "X" at 12035,3152.98 h60
  text "OTHER" at 12212.57,3151.73 h60
  text "3. MANUFACTURER'S IDENTIFICATION,DATECODE LETTER SHALL BE SILKSCREENED ON SOLDER SIDE OF THE BOARD." at 3563.89,3137.3 h60
  text "4. TRACE WIDTH SHOULD BE ACCURATELY ETCHED. MAX TOLERANCE +/- 1 MIL." at 3558.94,3000.97 h60
  text "ARRAY/PANEL:" at 10451.57,2996.35 h60
  text "CUT AND TRIM PER M1 BOARD OUTLINE" at 11512.57,2988.13 h60
  text "5. LAYER TO LAYER REGISTRATION SHALL BE WITHIN +/-2 MIL." at 3566,2876.86 h60
  text "N.C. ROUTE" at 11512.57,2852.16 h60
  text "V. SCORE" at 12378.57,2852.16 h60
  text "X" at 12195.57,2846.22 h60
  text "6. REFER IMPEDANCE TABLE FOR IMPEDANCE CONTROL TRACES ON LAYER 1, 3, 6 & 8." at 3557.02,2755.99 h60
  text "CERTIFICATION:" at 10451.57,2723.04 h60
  text "MATERIALS AND WORKMANSHIP FOR ALL PCBS" at 11176.57,2723.04 h60
  text "TO MEET OR EXCEED THE REQUIREMENTS OF:" at 11176.57,2628.97 h60
  text "7. FOR ACCURACY OF THE ANTENNA DIMENSION, NEED TO BE MEASURE THE  ANTENNA DIMENSIONS ON ONE BOARD" at 3554.84,2604.23 h60
  text "X" at 10814.08,2500.34 h60
  text "ANSI IPC-A-600F CLASS ->" at 10942.08,2500.34 h60
  text "X" at 12590.08,2500.34 h60
  text "2" at 12700.08,2500.34 h60
  text "1" at 12385.08,2498.85 h60
  text "3" at 13054.08,2498.85 h60
  text "8. ALL VIAS ARE TENTED ON BOTH SIDES UNLESS OTHERWISE SOLDER MASK OPENED IN GERBER." at 3548.41,2491.55 h60
  text "9. VIA HOLE OFFSET SHALL BE WITHIN 1MILS OF ITS ORIGINAL LOCATION" at 3552.35,2375.94 h60
  text "X" at 11626.08,2352.66 h60
  text "RoHS" at 11754.08,2352.66 h60
  text "OTHER" at 12398.48,2352.66 h60
  text "PER ORDER" at 12795.53,2352.66 h60
  text "ALL BOARDS MUST MEET OR EXCEED UL94-V0 REQUIREMENTS." at 10479.11,2198.83 h60
  text "C" at -1298.39,2197.76 h70
  text "C" at 13501.61,2197.76 h70
  text "PCB MUST BEAR THE UL94V-0 UL REGISTERED MATERIAL ID NUMBER" at 10479.11,2082.77 h60
  text "ADDITIONAL REQUIREMENTS:" at 10451.57,1913.34 h60
  text "MICROSECTION:" at 10526.34,1806.22 h60
  text "YES" at 11432.08,1806.22 h60
  text "REQUIRED" at 12293.57,1661.88 h60
  text "BARE BOARD ELEC. TEST:" at 10526.34,1659.03 h60
  text "NONE" at 11832.08,1659.03 h60
  text "X" at 12175.58,1659.03 h60
  text "PER ORDER" at 12885.57,1659.03 h60
  text "XX MIL VIAS REQUIRE NON-CONDUCTIVE FILL AND PLANARIZE" at 10710.11,1513.26 h59
  text "XX MIL VIAS REQUIRE CONDUCTIVE FILL AND PLANARIZE" at 10701.11,1354.26 h60
  text "OUTER XX MIL TRACES REQUIRE 50 OHM SINGLE-ENDED IMPEDANCE" at 10696.26,1211.37 h58
  text "LAYER 1 & 6 (INNER LAYERS) XX MIL WIDE, XX MIL SPACE" at 10735.11,961.26 h60
  text "PROJECT TITLE:" at 10461.61,336.76 h45
  text ".PRJ_Title" at 10511.61,203.44 h70
  text "DESIGNED FOR:" at 10461.61,35.76 h45
  text ".PRJ_Customer" at 10511.61,-104.24 h70
  text "D" at -1298.39,-172.24 h70
  text "D" at 13501.61,-172.24 h70
  text "REFER DETAIL-A" at 2636.78,-176.36 h40
  text "FILE NAME:" at 10461.61,-264.24 h45
  text ".PCB_File_Name_No_Path" at 10511.61,-384.24 h70
  text "Texas Instruments (TI) and/or its licensors do not warrant the accuracy or completeness of this specification" at 5492.11,-546.08 h45
  text "ENGINEER:" at 10461.61,-554.24 h45
  text "LAYOUT BY:" at 11966.61,-554.24 h45
  text "or any information contained therein. TI and/or its licensors do not warrant that this design will meet" at 5447.13,-658.74 h45
  text ".PRJ_Engineer" at 10511.61,-709.23 h70
  text ".PCB_Layout" at 12017.11,-709.23 h70
  text "the specifications, will be suitable for your application or fit for any particular purpose, or will operate in" at 5447.13,-771.41 h45
  text ".Layer_Name" at -307.48,-799.86 h60
  text "ALTIUM DESIGNER VERSION:" at 11966.61,-864.24 h45
  text "an implementation. TI and/or its licensors do not warrant that the design is production worthy. You should" at 5447.13,-884.07 h45
  text "completely validate and test your design implementation to confirm the system functionality for your application." at 5492.11,-996.74 h45
  text ".print_Scale" at 10511.61,-997.56 h70
  text ".Application_BuildNumber" at 12017.11,-997.56 h70
  text "1" at -142.05,-1204.24 h70
  text "2" at 2353.61,-1204.24 h70
  text "3" at 4842.96,-1204.24 h70
  text "4" at 7349.62,-1204.24 h70
  text "5" at 9848.61,-1204.24 h70
  text "6" at 12202.8,-1214.59 h70
M11 Gerber Information:
  lines w10: -1173.89,-870.9 5426.11,-870.9 ; -1173.89,-667.57 5428.11,-667.57 ; -1173.89,-464.24 -1173.89,-1074.24 2831.11,-1074.24 5428.11,-1074.24 5428.11,-464.24 -1173.39,-464.24 -1173.39,-1074.24 402.11,-1074.24 ; 1291.11,-1074.24 1291.11,-464.24 ; 2558.11,-667.57 2558.11,-464.24 ; 3398.11,-667.57 3398.11,-464.24 ; 4020.11,-1080.74 4020.11,-877.9
  text "ALL ARTWORK VIEWED FROM TOP SIDE" at -1110.39,-596.4 h60
  text "BOARD #:" at 1366.11,-596.4 h60
  text ".PRJ_Number" at 1911.61,-596.4 h60
  text "REV:" at 2756.11,-596.4 h60
  text ".PCB_Rev" at 3047.61,-596.4 h60
  text "SVN REV:" at 3594.11,-596.4 h60
  text ".VersionControl_RevNumber" at 4100.11,-596.4 h60
  text "LAYER NAME =" at -1110.39,-799.23 h60
  text "TID #:" at 1366.11,-799.74 h60
  text ".TID" at 1911.61,-799.74 h60
  text "PLOT NAME =" at -1110.39,-1005.07 h60
  text ".plot_File_Name" at -304.89,-1005.07 h60
  text "GENERATED    :" at 1368.11,-1005.07 h60
  text ".Print_Date" at 2237.61,-1005.07 h60
  text ".Print_Time" at 2966.61,-1005.07 h60
  text "TEXAS INSTRUMENTS" at 4231.11,-1005.07 h60
M12 Stackup:
  drawing of 566 lines, arcs and shapes, not listed
  text "NOTE :" at 6704.89,7352.9 h60
  text "1. THIS IS AN IMPEDANCE CONTROLLED BOARD." at 6888.39,7247.88 h60
  text "2. EXTERNAL LAYER CU THICKNESSES ARE FINISHED THICKNESS AFTER PLATING." at 6888.39,7150 h60
  text "6" at 8772.53,6987.31 h60
  text "IMPEDANCE TABLE :" at 7616.14,6971.93 h80
  text "LAYER" at 7114.38,6862.58 h70
  text "TRACE WIDTH" at 7401.59,6861.73 h70
  text "SPACING" at 7886.59,6861.73 h70
  text "IMPEDANCE +/- 10%" at 8221.59,6861.73 h70
  text "REFERENCE LAYER" at 8946.59,6861.73 h70
  text "TOP" at 7181.47,6703.59 h70
  text "9.3 MILS" at 7466.47,6698.59 h65
  text "5.3 MILS" at 7921.47,6698.59 h65
  text "50 OHM" at 8341.47,6698.59 h65
  text "LAYER-2 (GND LAYER)" at 8906.47,6698.59 h65
  text "LAYER" at 7113.42,6484.93 h70
  text "TRACE WIDTH" at 7400.62,6484.09 h70
  text "SPACING" at 7885.62,6484.09 h70
  text "IMPEDANCE +/- 10%" at 8220.62,6484.09 h70
  text "REFERENCE LAYER" at 8945.62,6484.09 h70
  text "5.2 MILS" at 7501.58,6324.09 h65
  text "5 MILS" at 7934.37,6324.09 h65
  text "100 OHM" at 8402.59,6324.09 h65
  text "LAYER-2" at 9085.16,6308.04 h65
  text "TOP" at 7122.32,6305.42 h70
  text "4.8 MILS" at 7500.83,6134.18 h65
  text "7.2 MIL" at 7928.87,6134.18 h65
  text "100 OHM" at 8402.59,6134.18 h65
  text "LAYER-2" at 9086.07,6131.79 h65
  text "L3" at 7144.05,6120.17 h70
  text "LAYER-2, LAYER 7" at 8959.85,5951.95 h65
  text "6 MILS" at 7500.83,5949.18 h65
  text "-" at 8018.22,5949.62 h65
  text "50 OHM" at 8402.59,5949.18 h65
  text "L3 & L6" at 7084.12,5936.72 h70
  text "LAYER-2" at 9093.55,5767.65 h65
  text "TOP" at 7132.59,5760.26 h70
  text "9.42 MILS" at 7492.4,5750.25 h65
  text "7 MILS" at 7925.66,5748.57 h65
  text "90 OHM" at 8386.86,5748.59 h65
  text "90 OHM" at 8382.93,5583.41 h65
  text "6 MILS" at 7483.97,5579.98 h65
  text "5 MILS" at 7930.71,5579.98 h65
  text "LAYER-7" at 9096.55,5578.62 h65
  text "BOTTOM" at 7088.32,5558.83 h60
  text "LAYER STACK-UP :" at 3546.15,2229.55 h80
  text "Layer" at 3606.13,1999.83 h60
  text "Name" at 4016.04,1999.83 h60
  text "Material" at 4945.79,1999.83 h60
  text "Thickness" at 7824.9,1999.83 h60
  text "Constant" at 8474.74,1999.83 h60
  text "Board Layer Stack" at 9044.6,1999.83 h60
  text "Top Overlay" at 4016.04,1879.83 h60
  text "Top Solder" at 4016.04,1759.83 h60
  text "Solder Resist" at 4945.79,1759.83 h60
  text "0.80mil" at 7824.9,1759.83 h60
  text "1" at 8474.74,1759.83 h60
  text "1" at 3606.13,1639.83 h60
  text "Top Layer" at 4016.04,1639.83 h60
  text "1.60mil" at 7824.9,1639.83 h60
  text "Dielectric 1" at 4016.04,1519.83 h60
  text "Isola FR408HR (DUAL PLY, 2x1067, SPREAD GLASS )" at 4945.79,1519.83 h60
  text "5.00mil" at 7824.9,1519.83 h60
  text "3.3" at 8474.74,1519.83 h60
  text "2" at 3606.13,1399.83 h60
  text "L2_GND1" at 4016.04,1399.83 h60
  text "1.20mil" at 7824.9,1399.83 h60
  text "Dielectric 2" at 4016.04,1279.83 h60
  text "PCL370HR" at 4945.79,1279.83 h60
  text "5.85mil" at 7824.9,1279.83 h60
  text "3.9" at 8474.74,1279.83 h60
  text "3" at 3606.13,1159.83 h60
  text "L3_SIG1" at 4016.04,1159.83 h60
  text "1.20mil" at 7824.9,1159.83 h60
  text "Dielectric 3" at 4016.04,1039.83 h60
  text "PCL370HR" at 4945.79,1039.83 h60
  text "10.00mil" at 7824.9,1039.83 h60
  text "4.25" at 8474.74,1039.83 h60
  text "4" at 3606.13,919.83 h60
  text "L4_PWR1" at 4016.04,919.83 h60
  text "1.20mil" at 7824.9,919.83 h60
  text "Dielectric 4" at 4016.04,799.83 h60
  text "PCL370HR" at 4945.79,799.83 h60
  text "5.65mil" at 7824.9,799.83 h60
  text "3.9" at 8474.74,799.83 h60
  text "5" at 3606.13,679.83 h60
  text "L5_PWR2" at 4016.04,679.83 h60
  text "1.20mil" at 7824.9,679.83 h60
  text "Dielectric 5" at 4016.04,559.83 h60
  text "PCL370HR" at 4945.79,559.83 h60
  text "10.00mil" at 7824.9,559.83 h60
  text "4.25" at 8474.74,559.83 h60
  text "6" at 3606.13,439.83 h60
  text "L6_SIG2" at 4016.04,439.83 h60
  text "1.20mil" at 7824.9,439.83 h60
  text "Dielectric 6" at 4016.04,319.83 h60
  text "PCL370HR" at 4945.79,319.83 h60
  text "5.50mil" at 7824.9,319.83 h60
  text "3.9" at 8474.74,319.83 h60
  text "7" at 3606.13,199.83 h60
  text "L7_GND2" at 4016.04,199.83 h60
  text "1.20mil" at 7824.9,199.83 h60
  text "Dielectric 7" at 4016.04,79.83 h60
  text "PCL370HR" at 4945.79,79.83 h60
  text "5.00mil" at 7824.9,79.83 h60
  text "4.25" at 8474.74,79.83 h60
  text "8" at 3606.13,-40.17 h60
  text "Bottom Layer" at 4016.04,-40.17 h60
  text "1.60mil" at 7824.9,-40.17 h60
  text "Bottom Solder" at 4016.04,-160.17 h60
  text "Solder Resist" at 4945.79,-160.17 h60
  text "0.80mil" at 7824.9,-160.17 h60
  text "1" at 8474.74,-160.17 h60
  text "Bottom Overlay" at 4016.04,-280.17 h60
  text ".Layer_Name" at -304.89,-799.23 h60
M13 Component Bodies Top:
  text ".Layer_Name" at -304.89,-799.23 h60
M14 Component Bodies Bottom:
  text ".Layer_Name" at -304.89,-799.23 h60
M15 Courtyards Top:
  text ".Layer_Name" at -304.89,-799.23 h60
M16 Courtyards Bottom:
  text ".Layer_Name" at -304.89,-799.23 h60
Drill Drawing:
  circle w10: c-961.93,6675.34 r33.33
  lines w10: -995.27,6258.67 -928.6,6258.67 -961.93,6192 -995.27,6258.67 ; -995.27,6508.67 -978.6,6508.67 -978.6,6492 -945.27,6492 -945.27,6508.67 -928.6,6508.67 -928.6,6542 -945.27,6542 -945.27,6558.67 -978.6,6558.67 -978.6,6542 -995.27,6542 -995.27,6508.67 ; -995.27,6792 -928.6,6792 -928.6,6858.67 -995.27,6858.67 -995.27,6792 ; -995.27,6942 -961.93,6958.67 -928.6,6942 -945.27,6975.34 -928.6,7008.67 -961.93,6992 -995.27,7008.67 -978.6,6975.34 -995.27,6942 ; -995.27,7108.67 -978.6,7108.67 -961.93,7092 -945.27,7108.67 -928.6,7108.67 -945.27,7125.34 -928.6,7142 -945.27,7142 -961.93,7158.67 -978.6,7142 -995.27,7142 -978.6,7125.34 -995.27,7108.67 ; -995.27,7242 -961.93,7258.67 -928.6,7242 -945.27,7275.34 -928.6,7308.67 -961.93,7292 -995.27,7308.67 -978.6,7275.34 -995.27,7242 ; -995.27,7425.34 -961.93,7392 -928.6,7425.34 -961.93,7458.67 -995.27,7425.34 ; -995.27,7542 -928.6,7542 -928.6,7608.67 -995.27,7608.67 -995.27,7542 ; -995.27,7708.67 -978.6,7708.67 -978.6,7692 -945.27,7692 -945.27,7708.67 -928.6,7708.67 -928.6,7742 -945.27,7742 -945.27,7758.67 -978.6,7758.67 -978.6,7742 -995.27,7742 -995.27,7708.67 ; -981.93,7115.34 -971.93,7115.34 -961.93,7105.34 -951.93,7115.34 -941.93,7115.34 -951.93,7125.34 -941.93,7135.34 -951.93,7135.34 -961.93,7145.34 -971.93,7135.34 -981.93,7135.34 -971.93,7125.34 -981.93,7115.34 ; -981.93,7255.34 -961.93,7265.34 -941.93,7255.34 -951.93,7275.34 -941.93,7295.34 -961.93,7285.34 -981.93,7295.34 -971.93,7275.34 -981.93,7255.34 ; -981.93,7555.34 -941.93,7555.34 -941.93,7595.34 -981.93,7595.34 -981.93,7555.34 ; -981.93,7715.34 -971.93,7715.34 -971.93,7705.34 -951.93,7705.34 -951.93,7715.34 -941.93,7715.34 -941.93,7735.34 -951.93,7735.34 -951.93,7745.34 -971.93,7745.34 -971.93,7735.34 -981.93,7735.34 -981.93,7715.34
  lines w15: -1055.06,6147 5673.06,6147 ; -1055.06,7797 5673.06,7797 ; -504.18,5997 -504.18,7947 ; 155.64,5997 155.64,7947 ; 1305.3,5997 1305.3,7947 ; 1811.18,5997 1811.18,7947 ; 3144.79,5997 3144.79,7947 ; 4478.39,5997 4478.39,7947 ; -1055.06,5997 5673.06,5997 5673.06,7947 -1055.06,7947 -1055.06,5997
  text "Symbol" at -965.06,7842 h72
  text "Count" at -459.18,7842 h72
  text "Hole Size" at 200.64,7842 h72
  text "Plated" at 1350.3,7842 h72
  text "Hole Tolerance (+)" at 1856.18,7842 h72
  text "Hole Tolerance (-)" at 3189.79,7842 h72
  text "Hole Length" at 4523.39,7842 h72
  text "1" at -459.18,7692 h60
  text "39.37mil (1.000mm)" at 200.64,7692 h60
  text "PTH" at 1350.3,7692 h60
  text "3.94mil (0.100mm)" at 1856.18,7692 h60
  text "3.94mil (0.100mm)" at 3189.79,7692 h60
  text "137.79mil (3.500mm)" at 4523.39,7692 h60
  text "2" at -459.18,7542 h60
  text "23.62mil (0.600mm)" at 200.64,7542 h60
  text "PTH" at 1350.3,7542 h60
  text "3.00mil (0.076mm)" at 1856.18,7542 h60
  text "3.00mil (0.076mm)" at 3189.79,7542 h60
  text "51.18mil (1.300mm)" at 4523.39,7542 h60
  text "2" at -459.18,7392 h60
  text "33.47mil (0.850mm)" at 200.64,7392 h60
  text "PTH" at 1350.3,7392 h60
  text "3.00mil (0.076mm)" at 1856.18,7392 h60
  text "3.00mil (0.076mm)" at 3189.79,7392 h60
  text "-" at 4523.39,7392 h60
  text "2" at -459.18,7242 h60
  text "39.37mil (1.000mm)" at 200.64,7242 h60
  text "PTH" at 1350.3,7242 h60
  text "3.94mil (0.100mm)" at 1856.18,7242 h60
  text "3.94mil (0.100mm)" at 3189.79,7242 h60
  text "118.11mil (3.000mm)" at 4523.39,7242 h60
  text "2" at -459.18,7092 h60
  text "40.16mil (1.020mm)" at 200.64,7092 h60
  text "NPTH" at 1350.3,7092 h60
  text "2.00mil (0.051mm)" at 1856.18,7092 h60
  text "2.00mil (0.051mm)" at 3189.79,7092 h60
  text "-" at 4523.39,7092 h60
  text "3" at -459.18,6942 h60
  text "43.31mil (1.100mm)" at 200.64,6942 h60
  text "PTH" at 1350.3,6942 h60
  text "3.00mil (0.076mm)" at 1856.18,6942 h60
  text "3.00mil (0.076mm)" at 3189.79,6942 h60
  text "-" at 4523.39,6942 h60
  text "4" at -459.18,6792 h60
  text "118.11mil (3.000mm)" at 200.64,6792 h60
  text "PTH" at 1350.3,6792 h60
  text "3.00mil (0.076mm)" at 1856.18,6792 h60
  text "3.00mil (0.076mm)" at 3189.79,6792 h60
  text "-" at 4523.39,6792 h60
  text "4" at -459.18,6642 h60
  text "160.00mil (4.064mm)" at 200.64,6642 h60
  text "NPTH" at 1350.3,6642 h60
  text "2.00mil (0.051mm)" at 1856.18,6642 h60
  text "2.00mil (0.051mm)" at 3189.79,6642 h60
  text "-" at 4523.39,6642 h60
  text "7" at -459.18,6492 h60
  text "23.62mil (0.600mm)" at 200.64,6492 h60
  text "PTH" at 1350.3,6492 h60
  text "3.00mil (0.076mm)" at 1856.18,6492 h60
  text "3.00mil (0.076mm)" at 3189.79,6492 h60
  text "-" at 4523.39,6492 h60
  text "10" at -459.18,6342 h60
  text "40.00mil (1.016mm)" at 200.64,6342 h60
  text "PTH" at 1350.3,6342 h60
  text "3.00mil (0.076mm)" at 1856.18,6342 h60
  text "3.00mil (0.076mm)" at 3189.79,6342 h60
  text "-" at 4523.39,6342 h60
  text "A" at -994.15,6332.01 h66.67
  text "2905" at -459.18,6192 h60
  text "8.00mil (0.203mm)" at 200.64,6192 h60
  text "PTH" at 1350.3,6192 h60
  text "3.00mil (0.076mm)" at 1856.18,6192 h60
  text "3.00mil (0.076mm)" at 3189.79,6192 h60
  text "-" at 4523.39,6192 h60
  text "2942 Total" at -459.18,6042 h60
  text "Slot definitions :" at -965.06,5897.03 h60
  text "Routed Path Length" at 67.63,5897.03 h60
  text "= Calculated from tool start centre position to tool end centre position." at 1170.3,5897.03 h60
  text "Hole Length" at 67.63,5797.05 h60
  text "= Routed Path Length + Tool Size = Slot length as defined in the PCB layout" at 760.43,5797.05 h60
  text ".Layer_Name" at -304.89,-799.23 h60
M17 Embedded Cavity:
  text ".Layer_Name" at -304.89,-799.23 h60
M18 Embedded Assembly:
  text ".Layer_Name" at -304.89,-799.23 h60
M19 Embedded Keepout:
  text ".Layer_Name" at -304.89,-799.23 h60
TX:
  lines w0.5: 1563.23,2681.94 1563.23,2732.37 1628.19,2732.37 1628.19,2681.94 1563.23,2681.94 ; 1563.23,2777.12 1563.23,2827.55 1628.19,2827.55 1628.19,2777.12 1601.62,2777.12 1601.62,2789.56 1589.8,2789.56 1589.8,2777.12 1563.23,2777.12 ; 1591.06,2622.33 1591.06,2642.02 1600.36,2642.02 1600.36,2622.33 1591.06,2622.33 ; 1591.34,2642.02 1591.34,2668.2 1600.08,2668.2 1600.08,2642.02 1591.34,2642.02 ; 1593.74,2668.2 1593.74,2694.77 1597.68,2694.77 1597.68,2668.2 1593.74,2668.2 ; 1593.74,2732.37 1593.74,2827.55 1597.68,2827.55 1597.68,2732.37 1593.74,2732.37 ; 1658.44,2681.94 1658.44,2732.37 1723.4,2732.37 1723.4,2681.94 1658.44,2681.94 ; 1658.44,2777.12 1658.44,2827.56 1723.4,2827.56 1723.4,2777.12 1696.83,2777.12 1696.83,2789.56 1685.02,2789.56 1685.02,2777.12 1658.44,2777.12 ; 1686.27,2622.33 1686.27,2642.02 1695.57,2642.02 1695.57,2622.33 1686.27,2622.33 ; 1686.55,2642.02 1686.55,2668.2 1695.29,2668.2 1695.29,2642.02 1686.55,2642.02 ; 1688.95,2668.2 1688.95,2694.77 1692.89,2694.77 1692.89,2668.2 1688.95,2668.2 ; 1688.95,2732.37 1688.95,2827.56 1692.89,2827.56 1692.89,2732.37 1688.95,2732.37
RX:
  lines w0.5: 1062.07,2791.38 1062.07,2841.81 1127.03,2841.81 1127.03,2791.38 1096.52,2791.38 1096.52,2777.64 1092.58,2777.64 1092.58,2791.38 1062.07,2791.38 ; 1062.07,2886.57 1062.07,2937 1127.03,2937 1127.03,2886.57 1100.46,2886.57 1100.46,2899.01 1088.65,2899.01 1088.65,2886.57 1062.07,2886.57 ; 1089.9,2731.78 1089.9,2751.46 1099.2,2751.46 1099.2,2731.78 1089.9,2731.78 ; 1090.18,2751.46 1090.18,2777.64 1098.92,2777.64 1098.92,2751.46 1090.18,2751.46 ; 1092.58,2841.81 1092.58,2937 1096.52,2937 1096.52,2841.81 1092.58,2841.81 ; 1157.26,2886.58 1187.77,2886.58 1187.77,2872.84 1191.7,2872.84 1191.7,2886.58 1222.22,2886.58 1222.22,2937.01 1157.26,2937.01 1157.26,2886.58 ; 1157.26,2981.76 1183.83,2981.76 1183.83,2994.2 1195.64,2994.2 1195.64,2981.76 1222.22,2981.76 1222.22,3032.2 1157.26,3032.2 1157.26,2981.76 ; 1185.09,2826.97 1194.39,2826.97 1194.39,2846.66 1185.09,2846.66 1185.09,2826.97 ; 1185.36,2846.66 1194.11,2846.66 1194.11,2872.84 1185.36,2872.84 1185.36,2846.66 ; 1187.77,2937.01 1191.7,2937.01 1191.7,3032.2 1187.77,3032.2 1187.77,2937.01 ; 1252.44,2791.38 1282.95,2791.38 1282.95,2777.64 1286.89,2777.64 1286.89,2791.38 1317.4,2791.38 1317.4,2841.81 1252.44,2841.81 1252.44,2791.38 ; 1252.44,2886.57 1279.01,2886.57 1279.01,2899.01 1290.83,2899.01 1290.83,2886.57 1317.4,2886.57 1317.4,2937 1252.44,2937 1252.44,2886.57 ; 1280.27,2731.78 1289.57,2731.78 1289.57,2751.46 1280.27,2751.46 1280.27,2731.78 ; 1280.55,2751.46 1289.29,2751.46 1289.29,2777.64 1280.55,2777.64 1280.55,2751.46 ; 1282.95,2841.81 1286.89,2841.81 1286.89,2937 1282.95,2937 1282.95,2841.81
